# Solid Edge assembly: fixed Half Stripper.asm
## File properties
Author: Dan
Template: metric assembly.asm
Last saved by: Dan
Revision: 16
Application: Solid Edge
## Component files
Succer Pin Dia 5 - 100.par
Stripper Plate.par
FH Clamping Plate.par
LP FSN34-36-126.par
Sprue Plate.par
SB M10-16.par
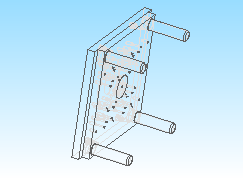
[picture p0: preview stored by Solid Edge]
